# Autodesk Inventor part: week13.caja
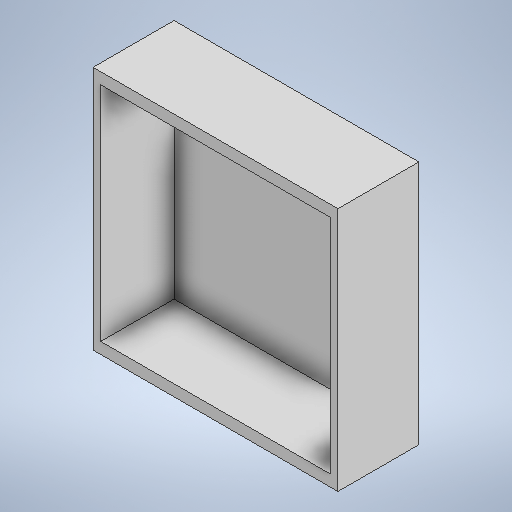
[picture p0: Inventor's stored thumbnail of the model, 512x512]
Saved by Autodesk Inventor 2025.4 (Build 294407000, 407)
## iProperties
Created: 2026-04
Part Number: week13.caja
Material: Generic
Document SubType Name: Modeling
Designer: FLB013
Density: 1 g/cm^3
Appearance: Default
Author: FLB013
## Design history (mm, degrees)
sketch "Sketch1"
  geometry: L1 (32.5, -32.5)-(-32.5, -32.5); L2 (-32.5, -32.5)-(-32.5, 32.5); L3 (-32.5, 32.5)-(32.5, 32.5); L4 (32.5, 32.5)-(32.5, -32.5); L5 (32.5, -32.5)-(-32.5, 32.5); L6 (-32.5, -32.5)-(32.5, 32.5); 1 further point
  constraints: 12 end point, 2 midpoint, 2 parallel, 1 horizontal, 1 perpendicular
  dimensions: "d0" = 65 distance of L2.end L3.end; "d1" = 65 distance of L1.end L2.end
extrude "Extrusion1" new body sketch "Sketch1" distance "d2" = 21.5; taper "d3" = 0 deg
shell "Shell1" dims "d4" = 3
feature "FaceDraft1" dims angle "d5" = 3 deg
body "Solid1"
